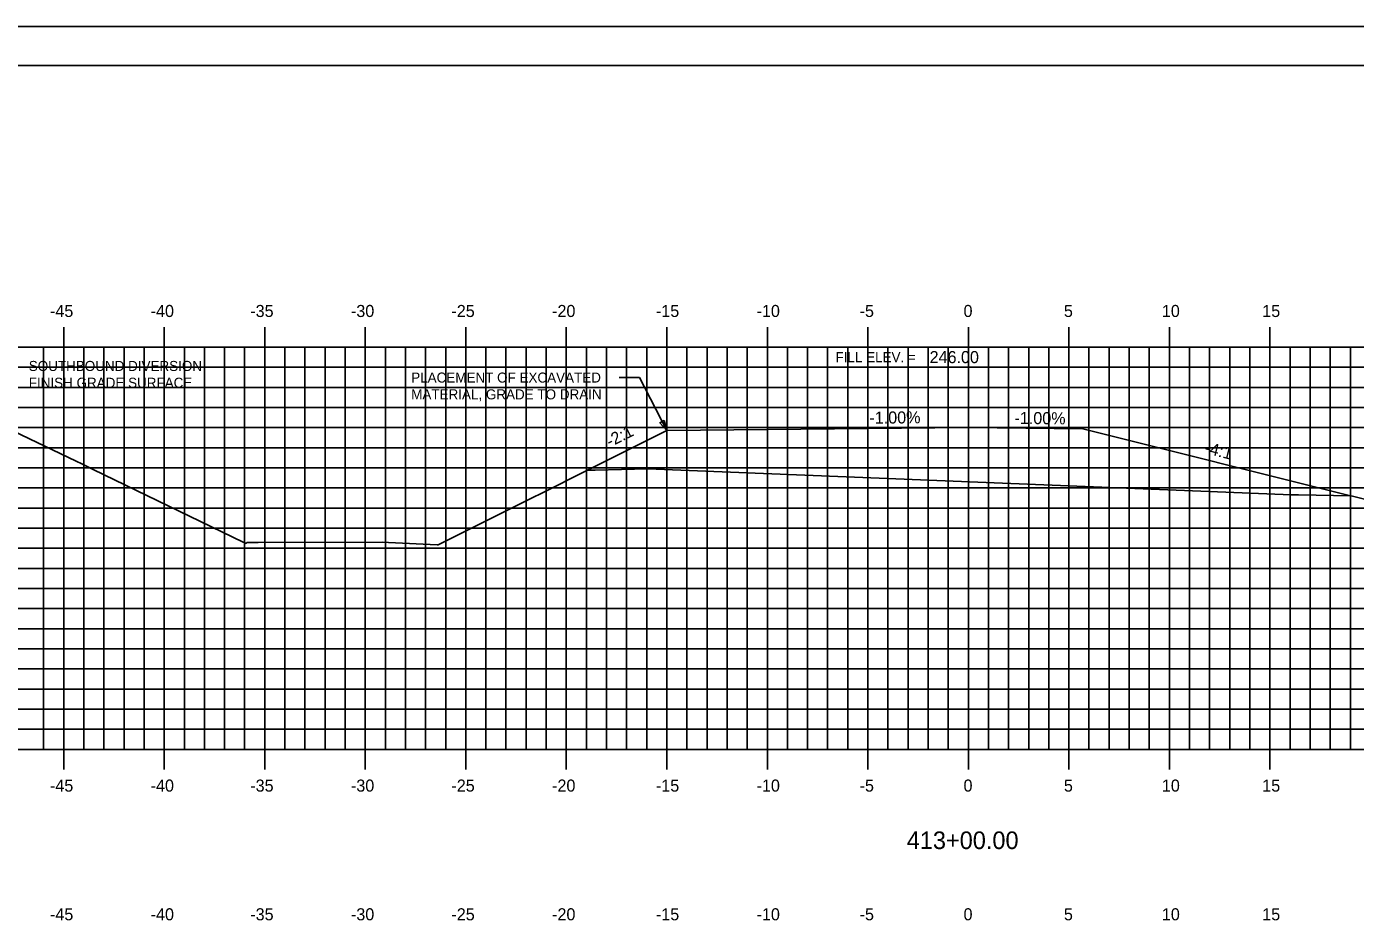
# Model space of a CAD drawing. Extents: x 1168600 to 1177589, y 610178 to 611246.
# Drawn here: x 1172477.5 to 1172543.6, y 610965.8 to 611010.5 of the extents above; entities that cross this region are included whole.
import ezdxf

# ---------------------------------------------------------------- set-up
doc = ezdxf.new("R2010")
doc.units = 0
for name, color, linetype in [('_Construction', 7, 'Continuous'), ('_Station Equation', 7, 'Continuous'), ('ANNOTATION', 7, 'Continuous'), ('BORDER', 7, 'Continuous'), ('D_Roadway_Centerline_Text', 7, 'Continuous'), ('D_Text_Standard', 7, 'Continuous'), ('H_V ANNOTATION', 7, 'Continuous'), ('MAJOR', 7, 'Continuous'), ('MINOR', 7, 'Continuous'), ('PLOT BOUNDARY', 7, 'Continuous')]:
    doc.layers.add(name, color=color, linetype=linetype)

msp = doc.modelspace()

# ---------------------------------------------------------------- linework, layer by layer
at = {"layer": '_Construction'}
for q in [(1172509.309, 610990.446), (1172530.001, 610990.539)]:
    msp.add_line((1172524.315, 610990.596), q, dxfattribs=at)
at = {"layer": '_Station Equation'}
msp.add_lwpolyline([(1172476.819, 610990.426), (1172479.939, 610988.92), (1172480.21, 610988.789), (1172480.774, 610988.517), (1172488.249, 610984.908), (1172488.267, 610984.9), (1172488.365, 610984.852), (1172488.39, 610984.841), (1172488.392, 610984.842), (1172488.441, 610984.883), (1172488.99, 610984.884), (1172495.178, 610984.893), (1172495.466, 610984.88), (1172497.892, 610984.77), (1172497.942, 610984.768), (1172502.688, 610987.141), (1172503.027, 610987.31), (1172505.364, 610988.479), (1172505.744, 610988.486), (1172508.364, 610988.539), (1172522.348, 610987.98), (1172524.364, 610987.899), (1172538.348, 610987.34), (1172540.364, 610987.259), (1172540.744, 610987.251), (1172543.364, 610987.199), (1172544.659, 610986.875)], dxfattribs=at)
at = {"layer": 'ANNOTATION'}
for p in [(1172506.951, 610993.085), (1172509.309, 610990.446)]:
    msp.add_line(p, (1172507.951, 610993.085), dxfattribs=at)
msp.add_lwpolyline([(1172509.191, 610990.948), (1172509.309, 610990.446), (1172508.969, 610990.834)], close=True, dxfattribs=at)
at = {"layer": 'BORDER'}
msp.add_line((1172609.315, 611008.596), (1172449.315, 611008.596), dxfattribs=at)
at = {"layer": 'D_Text_Standard'}
msp.add_lwpolyline([(1172505.326, 610988.455), (1172505.364, 610988.474), (1172509.309, 610990.446), (1172524.315, 610990.596), (1172530.001, 610990.539), (1172543.326, 610987.2)], dxfattribs=at)
at = {"layer": 'MAJOR'}
for p, q in [((1172479.315, 610995.598), (1172479.315, 610994.596)), ((1172484.315, 610995.598), (1172484.315, 610994.596)), ((1172489.315, 610995.598), (1172489.315, 610994.596)), ((1172494.315, 610995.598), (1172494.315, 610994.596)), ((1172499.315, 610995.598), (1172499.315, 610994.596)), ((1172504.315, 610995.598), (1172504.315, 610994.596)), ((1172509.315, 610995.598), (1172509.315, 610994.596)), ((1172514.315, 610995.598), (1172514.315, 610994.596)), ((1172519.315, 610995.598), (1172519.315, 610994.596)), ((1172524.315, 610995.598), (1172524.315, 610994.596)), ((1172529.315, 610995.598), (1172529.315, 610994.596)), ((1172534.315, 610995.598), (1172534.315, 610994.596)), ((1172539.315, 610995.598), (1172539.315, 610994.596)), ((1172454.315, 610994.596), (1172594.315, 610994.596)), ((1172454.315, 610994.596), (1172594.315, 610994.596)), ((1172479.315, 610974.596), (1172479.315, 610994.596)), ((1172484.315, 610974.596), (1172484.315, 610994.596)), ((1172489.315, 610974.596), (1172489.315, 610994.596)), ((1172494.315, 610974.596), (1172494.315, 610994.596)), ((1172499.315, 610974.596), (1172499.315, 610994.596)), ((1172504.315, 610974.596), (1172504.315, 610994.596)), ((1172509.315, 610974.596), (1172509.315, 610994.596)), ((1172514.315, 610974.596), (1172514.315, 610994.596)), ((1172519.315, 610974.596), (1172519.315, 610994.596)), ((1172524.315, 610974.596), (1172524.315, 610994.596)), ((1172529.315, 610974.596), (1172529.315, 610994.596)), ((1172534.315, 610974.596), (1172534.315, 610994.596)), ((1172539.315, 610974.596), (1172539.315, 610994.596)), ((1172454.315, 610989.596), (1172594.315, 610989.596)), ((1172454.315, 610984.596), (1172594.315, 610984.596)), ((1172454.315, 610979.596), (1172594.315, 610979.596)), ((1172454.315, 610974.596), (1172594.315, 610974.596)), ((1172454.315, 610974.596), (1172594.315, 610974.596)), ((1172479.315, 610973.594), (1172479.315, 610974.596)), ((1172484.315, 610973.594), (1172484.315, 610974.596)), ((1172489.315, 610973.594), (1172489.315, 610974.596)), ((1172494.315, 610973.594), (1172494.315, 610974.596)), ((1172499.315, 610973.594), (1172499.315, 610974.596)), ((1172504.315, 610973.594), (1172504.315, 610974.596)), ((1172509.315, 610973.594), (1172509.315, 610974.596)), ((1172514.315, 610973.594), (1172514.315, 610974.596)), ((1172519.315, 610973.594), (1172519.315, 610974.596)), ((1172524.315, 610973.594), (1172524.315, 610974.596)), ((1172529.315, 610973.594), (1172529.315, 610974.596)), ((1172534.315, 610973.594), (1172534.315, 610974.596)), ((1172539.315, 610973.594), (1172539.315, 610974.596))]:
    msp.add_line(p, q, dxfattribs=at)
at = {"layer": 'MINOR'}
for p, q in [((1172478.315, 610974.596), (1172478.315, 610994.596)), ((1172480.315, 610974.596), (1172480.315, 610994.596)), ((1172481.315, 610974.596), (1172481.315, 610994.596)), ((1172482.315, 610974.596), (1172482.315, 610994.596)), ((1172483.315, 610974.596), (1172483.315, 610994.596)), ((1172485.315, 610974.596), (1172485.315, 610994.596)), ((1172486.315, 610974.596), (1172486.315, 610994.596)), ((1172487.315, 610974.596), (1172487.315, 610994.596)), ((1172488.315, 610974.596), (1172488.315, 610994.596)), ((1172490.315, 610974.596), (1172490.315, 610994.596)), ((1172491.315, 610974.596), (1172491.315, 610994.596)), ((1172492.315, 610974.596), (1172492.315, 610994.596)), ((1172493.315, 610974.596), (1172493.315, 610994.596)), ((1172495.315, 610974.596), (1172495.315, 610994.596)), ((1172496.315, 610974.596), (1172496.315, 610994.596)), ((1172497.315, 610974.596), (1172497.315, 610994.596)), ((1172498.315, 610974.596), (1172498.315, 610994.596)), ((1172500.315, 610974.596), (1172500.315, 610994.596)), ((1172501.315, 610974.596), (1172501.315, 610994.596)), ((1172502.315, 610974.596), (1172502.315, 610994.596)), ((1172503.315, 610974.596), (1172503.315, 610994.596)), ((1172505.315, 610974.596), (1172505.315, 610994.596)), ((1172506.315, 610974.596), (1172506.315, 610994.596)), ((1172507.315, 610974.596), (1172507.315, 610994.596)), ((1172508.315, 610974.596), (1172508.315, 610994.596)), ((1172510.315, 610974.596), (1172510.315, 610994.596)), ((1172511.315, 610974.596), (1172511.315, 610994.596)), ((1172512.315, 610974.596), (1172512.315, 610994.596)), ((1172513.315, 610974.596), (1172513.315, 610994.596)), ((1172515.315, 610974.596), (1172515.315, 610994.596)), ((1172516.315, 610974.596), (1172516.315, 610994.596)), ((1172517.315, 610974.596), (1172517.315, 610994.596)), ((1172518.315, 610974.596), (1172518.315, 610994.596)), ((1172520.315, 610974.596), (1172520.315, 610994.596)), ((1172521.315, 610974.596), (1172521.315, 610994.596)), ((1172522.315, 610974.596), (1172522.315, 610994.596)), ((1172523.315, 610974.596), (1172523.315, 610994.596)), ((1172525.315, 610974.596), (1172525.315, 610994.596)), ((1172526.315, 610974.596), (1172526.315, 610994.596)), ((1172527.315, 610974.596), (1172527.315, 610994.596)), ((1172528.315, 610974.596), (1172528.315, 610994.596)), ((1172530.315, 610974.596), (1172530.315, 610994.596)), ((1172531.315, 610974.596), (1172531.315, 610994.596)), ((1172532.315, 610974.596), (1172532.315, 610994.596)), ((1172533.315, 610974.596), (1172533.315, 610994.596)), ((1172535.315, 610974.596), (1172535.315, 610994.596)), ((1172536.315, 610974.596), (1172536.315, 610994.596)), ((1172537.315, 610974.596), (1172537.315, 610994.596)), ((1172538.315, 610974.596), (1172538.315, 610994.596)), ((1172540.315, 610974.596), (1172540.315, 610994.596)), ((1172541.315, 610974.596), (1172541.315, 610994.596)), ((1172542.315, 610974.596), (1172542.315, 610994.596)), ((1172543.315, 610974.596), (1172543.315, 610994.596)), ((1172454.315, 610993.596), (1172594.315, 610993.596)), ((1172454.315, 610992.596), (1172594.315, 610992.596)), ((1172454.315, 610991.596), (1172594.315, 610991.596)), ((1172454.315, 610990.596), (1172594.315, 610990.596)), ((1172454.315, 610988.596), (1172594.315, 610988.596)), ((1172454.315, 610987.596), (1172594.315, 610987.596)), ((1172454.315, 610986.596), (1172594.315, 610986.596)), ((1172454.315, 610985.596), (1172594.315, 610985.596)), ((1172454.315, 610983.596), (1172594.315, 610983.596)), ((1172454.315, 610982.596), (1172594.315, 610982.596)), ((1172454.315, 610981.596), (1172594.315, 610981.596)), ((1172454.315, 610980.596), (1172594.315, 610980.596)), ((1172454.315, 610978.596), (1172594.315, 610978.596)), ((1172454.315, 610977.596), (1172594.315, 610977.596)), ((1172454.315, 610976.596), (1172594.315, 610976.596)), ((1172454.315, 610975.596), (1172594.315, 610975.596))]:
    msp.add_line(p, q, dxfattribs=at)
at = {"layer": 'PLOT BOUNDARY'}
msp.add_lwpolyline([(1172441.222, 610900.537), (1172611.222, 610900.537), (1172611.222, 611010.537), (1172441.222, 611010.537)], close=True, dxfattribs=at)

# ---------------------------------------------------------------- texts
at = {"layer": 'ANNOTATION'}
for s, p in [('FILL ELEV. =', (1172517.705, 610993.849)), ('SOUTHBOUND DIVERSION ', (1172477.577, 610993.412)), ('FINISH GRADE SURFACE', (1172477.577, 610992.577)), ('PLACEMENT OF EXCAVATED ', (1172496.6, 610992.835)), ('MATERIAL, GRADE TO DRAIN', (1172496.6, 610992))]:
    msp.add_text(s, height=0.5, dxfattribs=at).set_placement(p)
for s, rotation, p in [('-1.00%', 0.57294, (1172519.394, 610990.787)), ('-1.00%', 359.42706, (1172526.605, 610990.781)), ('-2:1', 26.56505, (1172506.481, 610989.604)), ('-4:1', 345.96376, (1172536.017, 610989.333))]:
    msp.add_text(s, height=0.6, rotation=rotation, dxfattribs=at).set_placement(p)
at = {"layer": 'D_Roadway_Centerline_Text'}
msp.add_text('246.00', height=0.6, dxfattribs=at).set_placement((1172522.386, 610993.803))
at = {"layer": 'H_V ANNOTATION'}
for s, height, p in [('-45', 0.6, (1172478.632, 610996.096)), ('-40', 0.6, (1172483.64, 610996.096)), ('-35', 0.6, (1172488.595, 610996.096)), ('-30', 0.6, (1172493.603, 610996.096)), ('-25', 0.6, (1172498.6, 610996.096)), ('-20', 0.6, (1172503.608, 610996.096)), ('-15', 0.6, (1172508.772, 610996.096)), ('-10', 0.6, (1172513.78, 610996.096)), ('-5', 0.6, (1172518.905, 610996.096)), ('0', 0.6, (1172524.074, 610996.096)), ('5', 0.6, (1172529.066, 610996.096)), ('10', 0.6, (1172533.94, 610996.096)), ('15', 0.6, (1172538.932, 610996.096)), ('-45', 0.6, (1172478.632, 610972.496)), ('-40', 0.6, (1172483.64, 610972.496)), ('-35', 0.6, (1172488.595, 610972.496)), ('-30', 0.6, (1172493.603, 610972.496)), ('-25', 0.6, (1172498.6, 610972.496)), ('-20', 0.6, (1172503.608, 610972.496)), ('-15', 0.6, (1172508.772, 610972.496)), ('-10', 0.6, (1172513.78, 610972.496)), ('-5', 0.6, (1172518.905, 610972.496)), ('0', 0.6, (1172524.074, 610972.496)), ('5', 0.6, (1172529.066, 610972.496)), ('10', 0.6, (1172533.94, 610972.496)), ('15', 0.6, (1172538.932, 610972.496)), ('413+00.00', 0.875, (1172521.248, 610969.639)), ('-45', 0.6, (1172478.632, 610966.096)), ('-40', 0.6, (1172483.64, 610966.096)), ('-35', 0.6, (1172488.595, 610966.096)), ('-30', 0.6, (1172493.603, 610966.096)), ('-25', 0.6, (1172498.6, 610966.096)), ('-20', 0.6, (1172503.608, 610966.096)), ('-15', 0.6, (1172508.772, 610966.096)), ('-10', 0.6, (1172513.78, 610966.096)), ('-5', 0.6, (1172518.905, 610966.096)), ('0', 0.6, (1172524.074, 610966.096)), ('5', 0.6, (1172529.066, 610966.096)), ('10', 0.6, (1172533.94, 610966.096)), ('15', 0.6, (1172538.932, 610966.096))]:
    msp.add_text(s, height=height, dxfattribs=at).set_placement(p)

doc.saveas('drawing.dxf')
